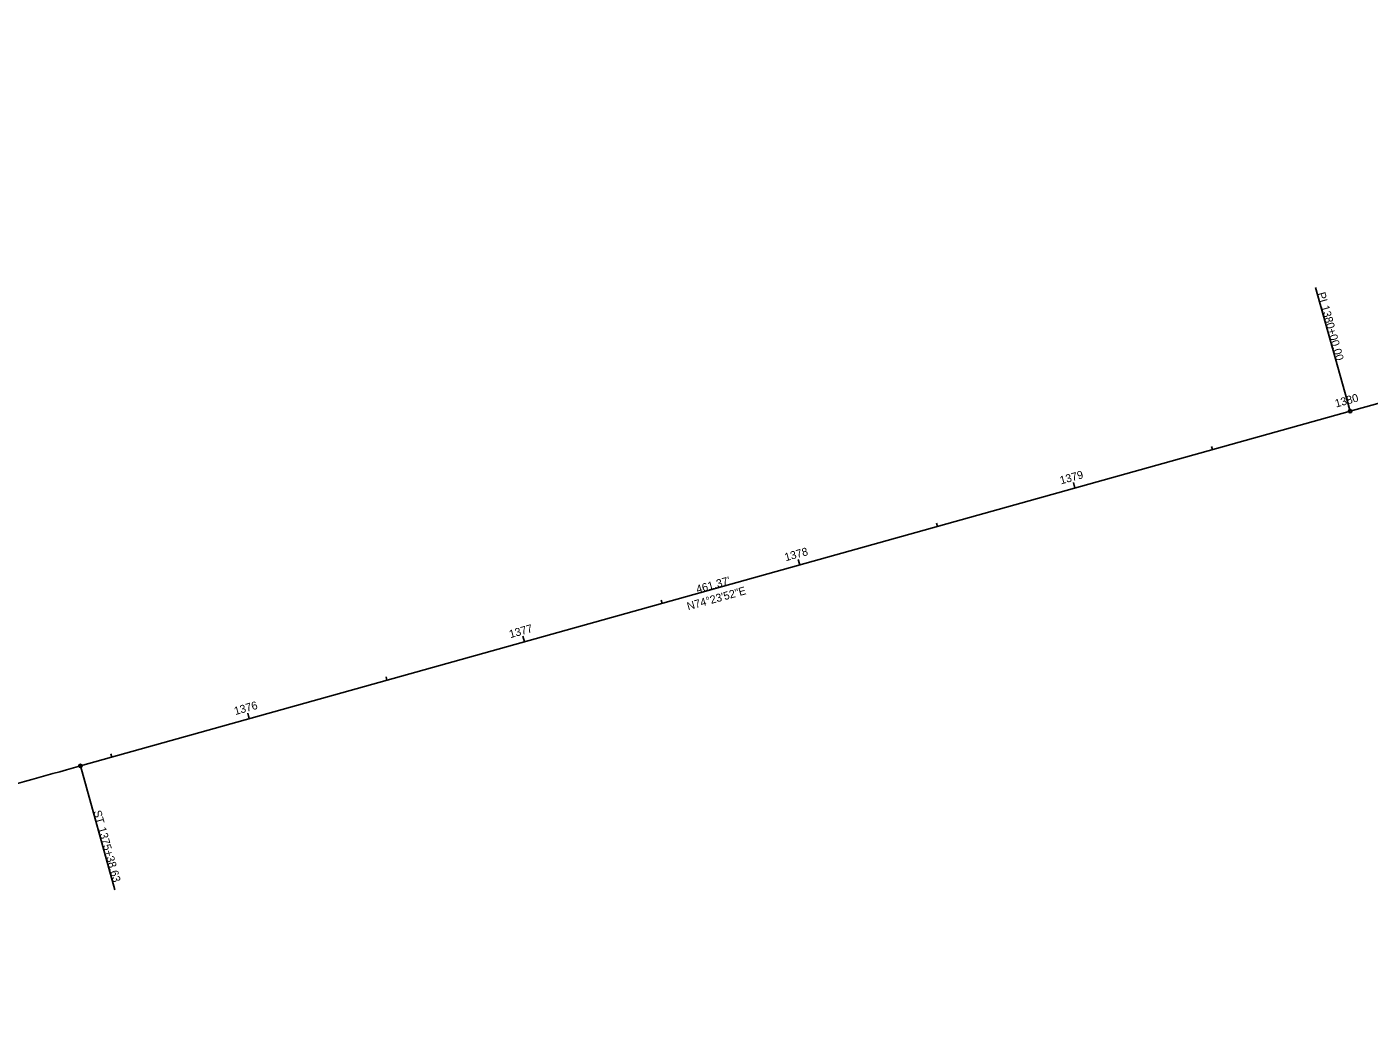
# Model space of a CAD drawing. Extents: x 153500 to 156291, y 370917 to 372075.
# Drawn here: x 155345.7 to 155815.5, y 371682 to 372030.9 of the extents above; entities that cross this region are included whole.
import ezdxf

# ---------------------------------------------------------------- set-up
doc = ezdxf.new("R2010")
doc.units = 0
for name, color, linetype in [('Default', 7, 'Continuous'), ('GE_X_Alignment', 7, 'Continuous'), ('GE_X_Alignment_1000_Stations', 7, 'Continuous'), ('GE_X_Alignment_100_Stations', 7, 'Continuous'), ('GE_X_Alignment_500_Stations', 7, 'Continuous')]:
    doc.layers.add(name, color=color, linetype=linetype)

msp = doc.modelspace()

# ---------------------------------------------------------------- linework, layer by layer
at = {"layer": 'Default'}
msp.add_line((155364.46, 371772.34), (155808.83, 371896.43), dxfattribs=at)
msp.add_open_spline([(155057.5, 371681.99), (155070.18, 371686.11), (155095.59, 371694.22), (155146.54, 371709.97), (155210.47, 371728.9), (155274.58, 371747.17), (155325.93, 371761.58), (155351.61, 371768.75), (155364.46, 371772.34)], degree=3, dxfattribs=at)
at = {"layer": 'GE_X_Alignment'}
for p, q in [((155808.83, 371896.43), (156290.4, 372030.91)), ((155364.46, 371772.34), (155808.83, 371896.43))]:
    msp.add_line(p, q, dxfattribs=at)
msp.add_open_spline([(155057.5, 371681.99), (155070.18, 371686.11), (155095.59, 371694.22), (155146.54, 371709.97), (155210.47, 371728.9), (155274.58, 371747.17), (155325.93, 371761.58), (155351.61, 371768.75), (155364.46, 371772.34)], degree=3, dxfattribs=at)
at = {"layer": 'GE_X_Alignment_1000_Stations'}
for p, q in [((155808.83, 371896.43), (155796.73, 371939.77)), ((155808.83, 371896.43), (155808.29, 371898.36)), ((155364.46, 371772.34), (155376.56, 371729))]:
    msp.add_line(p, q, dxfattribs=at)
for centre in [(155808.83, 371896.43), (155364.46, 371772.34)]:
    msp.add_circle(centre, 0.6, dxfattribs=at)
at = {"layer": 'GE_X_Alignment_100_Stations'}
for p, q in [((155808.83, 371896.43), (155796.73, 371939.77)), ((155808.83, 371896.43), (155808.29, 371898.36)), ((155760.67, 371882.98), (155760.35, 371884.14)), ((155712.52, 371869.53), (155711.98, 371871.46)), ((155664.36, 371856.09), (155664.04, 371857.24)), ((155616.2, 371842.64), (155615.66, 371844.57)), ((155568.04, 371829.19), (155567.72, 371830.35)), ((155519.89, 371815.74), (155519.35, 371817.67)), ((155471.73, 371802.3), (155471.41, 371803.45)), ((155423.57, 371788.85), (155423.03, 371790.77)), ((155375.41, 371775.4), (155375.09, 371776.56)), ((155364.46, 371772.34), (155376.56, 371729))]:
    msp.add_line(p, q, dxfattribs=at)
for centre in [(155808.83, 371896.43), (155364.46, 371772.34)]:
    msp.add_circle(centre, 0.6, dxfattribs=at)
at = {"layer": 'GE_X_Alignment_500_Stations'}
for p, q in [((155808.83, 371896.43), (155796.73, 371939.77)), ((155808.83, 371896.43), (155808.29, 371898.36)), ((155712.52, 371869.53), (155712.19, 371870.69)), ((155616.2, 371842.64), (155615.88, 371843.79)), ((155519.89, 371815.74), (155519.56, 371816.9)), ((155423.57, 371788.85), (155423.25, 371790)), ((155364.46, 371772.34), (155376.56, 371729))]:
    msp.add_line(p, q, dxfattribs=at)
for centre in [(155808.83, 371896.43), (155364.46, 371772.34)]:
    msp.add_circle(centre, 0.6, dxfattribs=at)

# ---------------------------------------------------------------- texts
at = {"layer": 'GE_X_Alignment_1000_Stations'}
for s, rotation, p in [('PI', 285.6022, (155797.36, 371937.66)), ('1380+00.00', 285.6022, (155798.65, 371933.05)), ('1380', 15.6022, (155803.94, 371897.71)), ("461.37'", 15.6022, (155580.38, 371832.69)), ('N74°23\'52"E', 15.6022, (155577.17, 371826.75)), ('ST', 285.6022, (155368.96, 371756.39)), ('1375+38.63', 285.6022, (155370.6, 371750.53))]:
    msp.add_text(s, height=2.8, rotation=rotation, dxfattribs=at).set_placement(p)
at = {"layer": 'GE_X_Alignment_100_Stations'}
for s, rotation, p in [('PI', 285.6022, (155797.36, 371937.66)), ('1380+00.00', 285.6022, (155798.65, 371933.05)), ('1380', 15.6022, (155803.94, 371897.71)), ('1379', 15.6022, (155707.65, 371870.82)), ('1378', 15.6022, (155611.31, 371843.92)), ("461.37'", 15.6022, (155580.38, 371832.69)), ('N74°23\'52"E', 15.6022, (155577.17, 371826.75)), ('1377', 15.6022, (155514.94, 371817.01)), ('1376', 15.6022, (155418.68, 371790.12)), ('ST', 285.6022, (155368.96, 371756.39)), ('1375+38.63', 285.6022, (155370.6, 371750.53))]:
    msp.add_text(s, height=2.8, rotation=rotation, dxfattribs=at).set_placement(p)
at = {"layer": 'GE_X_Alignment_500_Stations'}
for s, rotation, p in [('PI', 285.6022, (155797.36, 371937.66)), ('1380+00.00', 285.6022, (155798.65, 371933.05)), ('1380', 15.6022, (155803.94, 371897.71)), ("461.37'", 15.6022, (155580.38, 371832.69)), ('N74°23\'52"E', 15.6022, (155577.17, 371826.75)), ('ST', 285.6022, (155368.96, 371756.39)), ('1375+38.63', 285.6022, (155370.6, 371750.53))]:
    msp.add_text(s, height=2.8, rotation=rotation, dxfattribs=at).set_placement(p)

doc.saveas('drawing.dxf')
